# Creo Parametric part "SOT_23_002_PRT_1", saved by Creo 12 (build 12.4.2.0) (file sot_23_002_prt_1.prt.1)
Units: Custom; MM, KILOGRAM, SECS

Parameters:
  PTC_WM_ITERATION = "0"
  PTC_WM_VERSION = "-.0"
  PTC_WM_LIFECYCLE_STATE = "In Work"
  PTC_WM_LIFECYCLE = "MO_CADDocument"
  PTC_WM_CREATED_BY = "Maximilian Roepper (Z0017RMS: MO)"
  PTC_WM_CREATED_ON = "18-Sep-26 11:36:42 AM"
  PTC_WM_MODIFIED_BY = "Maximilian Roepper (Z0017RMS: MO)"
  PTC_WM_MODIFIED_ON = "18-Sep-26 11:36:46 AM"
  PDMLINKNUMBER = "PDM000071455036"
  PTC_WM_NAME = "sot_23_002_prt_1.prt"
  PTC_WM_NUMBER = "PDM000071455036"

Other parameters: WEIGHT, WEIGHT_FACTOR, WEIGHT_ADD, _MASS_TEMP, _DIFF_TEMP, MC_ERRORS, SUPPLIER

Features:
  1. coordinate system
  2. datum plane "PRT_YZ"
  3. datum plane "PRT_XY"
  4. datum plane "PRT_XZ"
  5. coordinate system
  6. datum axis
  7. datum axis
  8. datum axis
  9. coordinate system
  10. imported feature
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
Other named items: PRT, SIEMENS_MO, DRW_VIEW_ORG, PRT_X, PRT_Y, PRT_Z, CS0, ROUGH_GROB

Layers: 00_STD_CSYS-KSYS, 01_STD_PLANES-EBENEN, 02_STD_AXES-ACHSEN, 03_STD_CSYS-KSYS, 24_IMPORT_FEAT-IMPORT_KE

Surfaces: 64 plane, 12 cylinder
